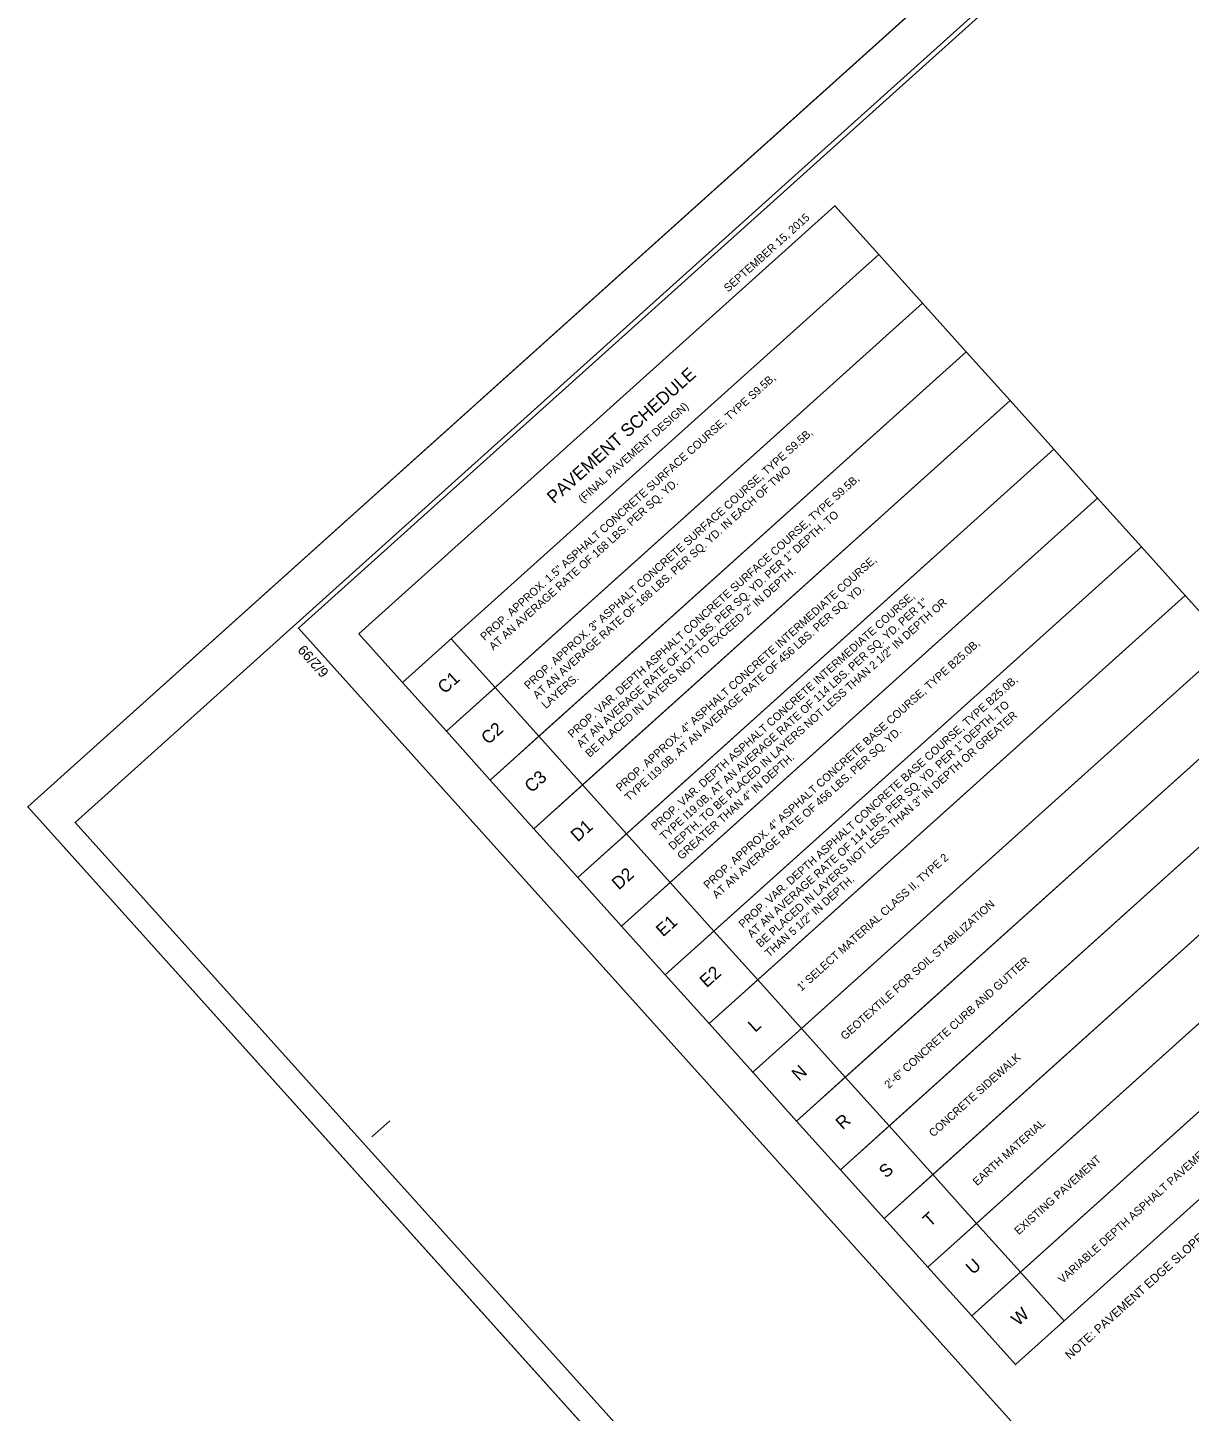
# Model space of a CAD drawing. Extents: x 2488411 to 2488707, y 383669 to 383962.
# Drawn here: x 2488468.9 to 2488541.5, y 383788.8 to 383875.2 of the extents above; entities that cross this region are included whole.
import ezdxf

# ---------------------------------------------------------------- set-up
doc = ezdxf.new("R2010")
doc.units = 0
for name, color, linetype in [('Old_Level_19', 7, 'Continuous'), ('Old_Level_21', 7, 'Continuous'), ('Prop Grid Mask', 7, 'Continuous'), ('Prop XS SE Text', 7, 'Continuous'), ('Sheet Cutting Line CELL', 7, 'Continuous'), ('Sheet Title CELL', 7, 'Continuous')]:
    doc.layers.add(name, color=color, linetype=linetype)

msp = doc.modelspace()

# ---------------------------------------------------------------- linework, layer by layer
at = {"layer": 'Old_Level_19'}
msp.add_lwpolyline([(2488619.231, 383961.604), (2488468.948, 383826.508), (2488557.194, 383728.341), (2488707.477, 383863.438)], close=True, dxfattribs=at)
at = {"layer": 'Old_Level_21'}
msp.add_lwpolyline([(2488620.631, 383959.24), (2488471.909, 383825.547), (2488556.553, 383731.388), (2488705.275, 383865.081)], close=True, dxfattribs=at)
at = {"layer": 'Prop Grid Mask'}
msp.add_lwpolyline([(2488489.633, 383837.318), (2488519.381, 383864.06), (2488522.116, 383861.018), (2488492.368, 383834.276)], close=True, dxfattribs=at)
for points in [[(2488498.146, 383833.968), (2488495.103, 383831.233), (2488492.368, 383834.276), (2488522.115, 383861.017), (2488524.851, 383857.974), (2488498.146, 383833.968), (2488495.41, 383837.011)], [(2488500.881, 383830.925), (2488497.839, 383828.19), (2488495.103, 383831.233), (2488524.851, 383857.974), (2488527.586, 383854.931), (2488500.881, 383830.925), (2488498.146, 383833.968)], [(2488503.616, 383827.882), (2488500.574, 383825.148), (2488497.839, 383828.19), (2488527.586, 383854.931), (2488530.321, 383851.889), (2488503.616, 383827.882), (2488500.881, 383830.925)], [(2488506.351, 383824.84), (2488503.309, 383822.105), (2488500.574, 383825.148), (2488530.321, 383851.889), (2488533.056, 383848.847), (2488506.351, 383824.84), (2488503.616, 383827.882)], [(2488509.086, 383821.798), (2488506.043, 383819.063), (2488503.309, 383822.105), (2488533.057, 383848.847), (2488535.791, 383845.805), (2488509.086, 383821.798), (2488506.351, 383824.84)], [(2488511.821, 383818.756), (2488508.778, 383816.021), (2488506.043, 383819.063), (2488535.791, 383845.804), (2488538.526, 383842.762), (2488511.821, 383818.756), (2488509.086, 383821.798)], [(2488514.555, 383815.713), (2488511.513, 383812.978), (2488508.778, 383816.021), (2488538.526, 383842.762), (2488541.261, 383839.72), (2488514.555, 383815.713), (2488511.821, 383818.756)], [(2488517.29, 383812.671), (2488514.248, 383809.936), (2488511.513, 383812.978), (2488541.261, 383839.72), (2488543.996, 383836.678), (2488517.29, 383812.671), (2488514.555, 383815.713)], [(2488520.025, 383809.629), (2488516.983, 383806.894), (2488514.248, 383809.936), (2488543.996, 383836.678), (2488546.731, 383833.636), (2488520.025, 383809.629), (2488517.29, 383812.671)], [(2488522.76, 383806.586), (2488519.718, 383803.852), (2488516.983, 383806.894), (2488546.731, 383833.636), (2488549.466, 383830.593), (2488522.76, 383806.586), (2488520.025, 383809.629)], [(2488525.495, 383803.544), (2488522.453, 383800.809), (2488519.718, 383803.852), (2488549.465, 383830.593), (2488552.2, 383827.551), (2488525.495, 383803.544), (2488522.76, 383806.586)], [(2488528.23, 383800.502), (2488525.187, 383797.767), (2488522.453, 383800.809), (2488552.2, 383827.551), (2488554.935, 383824.508), (2488528.23, 383800.502), (2488525.495, 383803.544)], [(2488530.965, 383797.46), (2488527.922, 383794.725), (2488525.187, 383797.767), (2488554.935, 383824.508), (2488557.67, 383821.466), (2488530.965, 383797.46), (2488528.23, 383800.502)], [(2488533.699, 383794.417), (2488530.657, 383791.682), (2488527.922, 383794.725), (2488557.67, 383821.466), (2488560.404, 383818.424), (2488533.699, 383794.417), (2488530.965, 383797.46)]]:
    msp.add_lwpolyline(points, dxfattribs=at)
at = {"layer": 'Prop XS SE Text'}
for p, q in [((2488619.231, 383961.604), (2488468.948, 383826.508)), ((2488468.948, 383826.508), (2488557.194, 383728.341))]:
    msp.add_line(p, q, dxfattribs=at)
at = {"layer": 'Sheet Cutting Line CELL'}
msp.add_line((2488490.454, 383805.904), (2488491.569, 383806.907), dxfattribs=at)
msp.add_lwpolyline([(2488619.72, 383958.009), (2488485.857, 383837.674), (2488570.092, 383743.97), (2488703.955, 383864.305)], close=True, dxfattribs=at)

# ---------------------------------------------------------------- texts
at = {"layer": 'Prop Grid Mask'}
for s, height, p in [('PROP. APPROX. 1.5" ASPHALT CONCRETE SURFACE COURSE, TYPE S9.5B, ', 0.5, (2488497.498, 383836.87)), ('PAVEMENT SCHEDULE', 0.8, (2488501.831, 383845.409)), ('PROP. APPROX. 3" ASPHALT CONCRETE SURFACE COURSE, TYPE S9.5B, ', 0.5, (2488500.233, 383833.827)), ('AT AN AVERAGE RATE OF 168 LBS. PER SQ. YD. IN EACH OF TWO ', 0.5, (2488500.779, 383833.22)), ('PROP. VAR. DEPTH ASPHALT CONCRETE SURFACE COURSE, TYPE S9.5B,', 0.5, (2488502.969, 383830.784)), ('AT AN AVERAGE RATE OF 168 LBS. PER SQ. YD.', 0.5, (2488498.043, 383836.263)), ('AT AN AVERAGE RATE OF 112 LBS. PER SQ. YD. PER 1" DEPTH. TO', 0.5, (2488503.514, 383830.177)), ('PROP. APPROX. 4" ASPHALT CONCRETE INTERMEDIATE COURSE,', 0.5, (2488505.968, 383827.442)), ('BE PLACED IN LAYERS NOT TO EXCEED 2" IN DEPTH.', 0.5, (2488504.059, 383829.571)), ('TYPE I19.0B, AT AN AVERAGE RATE OF 456 LBS. PER SQ. YD.', 0.5, (2488506.513, 383826.835)), ('PROP. VAR. DEPTH ASPHALT CONCRETE INTERMEDIATE COURSE,', 0.5, (2488508.165, 383825.003)), ('TYPE I19.0B, AT AN AVERAGE RATE OF 114 LBS. PER SQ. YD. PER 1" ', 0.5, (2488508.711, 383824.397)), ('DEPTH, TO BE PLACED IN LAYERS NOT LESS THAN 2 1/2" IN DEPTH OR', 0.5, (2488509.256, 383823.79)), ('PROP. APPROX. 4" ASPHALT CONCRETE BASE COURSE, TYPE B25.0B,', 0.5, (2488511.443, 383821.357)), ('C1', 0.8, (2488494.995, 383833.532)), ('LAYERS.', 0.5, (2488501.324, 383832.614)), ('PROP. VAR. DEPTH ASPHALT CONCRETE BASE COURSE, TYPE B25.0B,', 0.5, (2488513.635, 383818.919)), ('AT AN AVERAGE RATE OF 114 LBS. PER SQ. YD. PER 1" DEPTH. TO', 0.5, (2488514.18, 383818.312)), ('BE PLACED IN LAYERS NOT LESS THAN 3" IN DEPTH OR GREATER', 0.5, (2488514.726, 383817.705)), ('C2', 0.8, (2488497.716, 383830.363)), ('AT AN AVERAGE RATE OF 456 LBS. PER SQ. YD.', 0.5, (2488511.989, 383820.75)), ('GREATER THAN 4" IN DEPTH.', 0.5, (2488509.801, 383823.183)), ('C3', 0.8, (2488500.423, 383827.352)), ('D1', 0.8, (2488503.308, 383824.286)), ("1' SELECT MATERIAL CLASS II, TYPE 2", 0.5, (2488517.273, 383814.97)), ('D2', 0.8, (2488505.876, 383821.286)), ('THAN 5 1/2" IN DEPTH.', 0.5, (2488515.271, 383817.099)), ('GEOTEXTILE FOR SOIL STABILIZATION', 0.5, (2488520.008, 383811.927)), ('E1', 0.8, (2488508.637, 383818.357)), ('2\'-6" CONCRETE CURB AND GUTTER', 0.5, (2488522.743, 383808.885)), ('E2', 0.8, (2488511.365, 383815.18)), ('L', 0.8, (2488514.392, 383812.393)), ('CONCRETE SIDEWALK', 0.5, (2488525.526, 383805.862)), ('VARIABLE DEPTH ASPHALT PAVEMENT (SEE WEDGING DETAIL)', 0.5, (2488533.595, 383796.715)), ('N', 0.8, (2488517.127, 383809.351)), ('NOTE: PAVEMENT EDGE SLOPES ARE 1:1 UNLESS SHOWN OTHERWISE.', 0.54417, (2488534.06, 383791.963)), ('R', 0.8, (2488519.862, 383806.309)), ('EARTH MATERIAL', 0.5, (2488528.261, 383802.819)), ('EXISTING PAVEMENT', 0.5, (2488530.86, 383799.757)), ('S', 0.8, (2488522.57, 383803.283)), ('T', 0.8, (2488525.305, 383800.24)), ('U', 0.8, (2488527.999, 383797.259)), ('W', 0.8, (2488530.827, 383794.05))]:
    msp.add_text(s, height=height, rotation=41.95382, dxfattribs=at).set_placement(p)
at = {"layer": 'Sheet Cutting Line CELL'}
msp.add_text('6/2/99', height=0.63, rotation=131.95382, dxfattribs=at).set_placement((2488487.802, 383834.945))
at = {"layer": 'Sheet Title CELL'}
for s, p in [('SEPTEMBER 15, 2015', (2488512.707, 383858.638)), ('(FINAL PAVEMENT DESIGN)', (2488503.623, 383845.475))]:
    msp.add_text(s, height=0.5, rotation=41.95382, dxfattribs=at).set_placement(p)

doc.saveas('drawing.dxf')
